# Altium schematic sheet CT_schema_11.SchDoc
size 147 x 119 mm
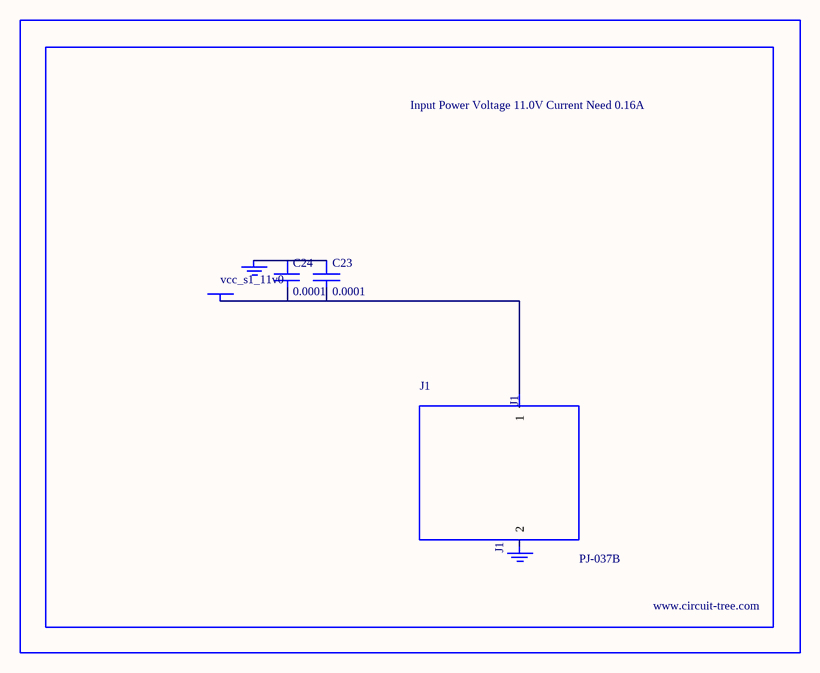
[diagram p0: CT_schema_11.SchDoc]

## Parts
BORDER10  (no value)
C23  0.0001  [EXV-9H]
C24  0.0001  [EXV-9H]
GND_INSTANCE_10_0  (no value)
GND_INSTANCE_10_1  (no value)
J1  PJ-037B  [PJ-037B_PACKAGE]
POWER_INSTANCE_10_0  vcc_s1_11v0

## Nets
NetC23_1: C23.1 C24.1 GND_INSTANCE_10_0.0(GND)
NetC23_2: C23.2 C24.2 J1.1 POWER_INSTANCE_10_0.0(PWR)

Not connected (* = marked no-connect by the designer): GND_INSTANCE_10_1 0(GND); J1 2

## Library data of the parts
BORDER10 = BORDER_PAGE10
C23 C24 = EDK107M035A9HAA
GND_INSTANCE_10_0 GND_INSTANCE_10_1 = GND
POWER_INSTANCE_10_0 = PWR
